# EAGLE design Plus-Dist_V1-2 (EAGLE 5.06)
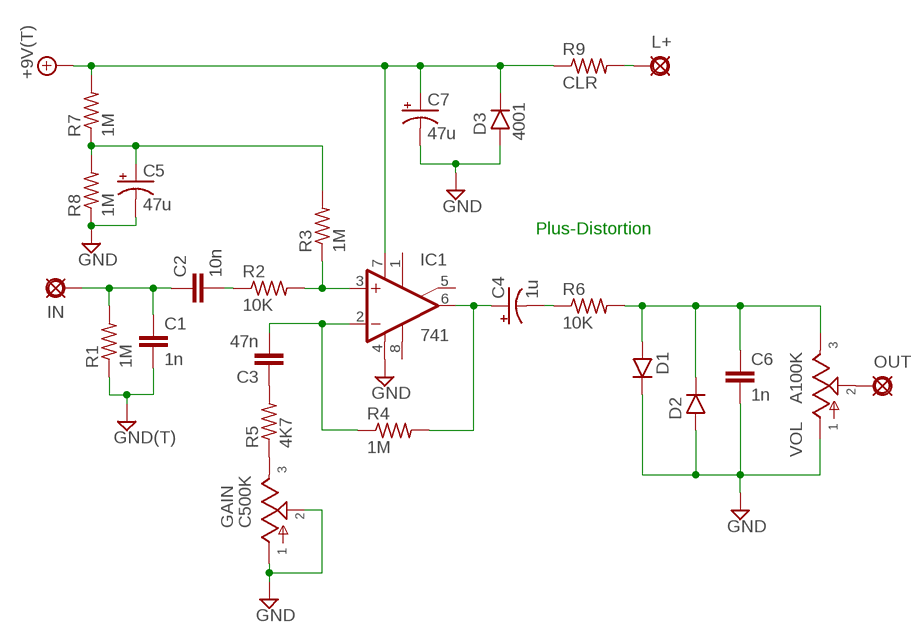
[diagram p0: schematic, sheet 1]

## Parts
+9V  +9V(T)  [SQUARE]
C1  1n  072X0252  [072X025]
C2  10n  072X0252  [072X025]
C3  47n  072X0252  [072X025]
C4  1u  0501  [050_020_1]
C5  47u  0501  [050_020_1]
C6  1n  072X0252  [072X025]
C7  47u  0501  [050_020_1]
D1  1N400X.4  [DO41-4]
D2  1N400X.4  [DO41-4]
D3  4001  1N400X.3  [DO41-3]
GAIN  C500K  POTPCB  [16MM-PCB-MOUNT]
GND  GND(T)  [SQUARE]
IC1  741  uA741P  [DIL08]
IN  PAD8  [OCTOGON]
L+  L+  PAD8  [OCTOGON]
OUT  PAD8  [OCTOGON]
R1  1M  6MM.3  [R0207/3]
R2  10K  6MM.3  [R0207/3]
R3  1M  6MM.3  [R0207/3]
R4  1M  6MM.3  [R0207/3]
R5  4K7  6MM.3  [R0207/3]
R6  10K  6MM.3  [R0207/3]
R7  1M  6MM.3  [R0207/3]
R8  1M  6MM.3  [R0207/3]
R9  CLR  6MM.3  [R0207/3]
VOL  A100K  POTPCB  [16MM-PCB-MOUNT]

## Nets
+9V: +9V.1(+9V) C7.+ D3.C IC1.7(V+) R7.2 R9.1
GND: C1.2 C5.- C6.2 C7.- D1.C D2.A D3.A GAIN.1 GAIN.2 GND.1(GND) IC1.4(V-) R1.1 R8.1 VOL.1
N$1: C1.1 C2.1 IN.1(PAD) R1.2
N$2: C2.2 R2.1
N$3: IC1.3(+IN) R2.2 R3.1
N$4: C3.2 IC1.2(-IN) R4.1
N$5: C4.+ IC1.6(OUT) R4.2
N$6: C3.1 R5.2
N$7: GAIN.3 R5.1
N$8: C4.- R6.1
N$9: C5.+ R3.2 R7.1 R8.2
N$10: OUT.1(PAD) VOL.2
N$11: C6.1 D1.A D2.C R6.2 VOL.3
N$12: L+.1(PAD) R9.2
Unconnected: IC1.1(ON1) IC1.5(ON2) IC1.8(OPT)

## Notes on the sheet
- Plus-Distortion

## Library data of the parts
+9V = gm-supply:+9V(T): +9V Voltage Supply
C1-C3 C6 = gm-caps-film-box:072X025: 1000pF - 0.47uF
C4 C5 C7 = gm-caps-electro-pol:050: 0.22 - 100uF
D1-D3 = gm-diodes:1N400X: Rectifier Diodes
GAIN VOL = gm-pots_pcb_noscreen:POT: Potentiometers the arrow indicates the clockwise motion of th wiper (lug 2) fully counter clockwise there is no resistance between lugs 1 and 2 fully clockwise the resistance between lugs 1 and 2 is the value of the pot
GND = gm-supply:GND(T): Ground
IC1 = gm-ics:*741: OP AMP
IN L+ OUT = gm-supply:PAD: PAD
R1-R9 = gm-resistors:6MM: 6mm Resistors

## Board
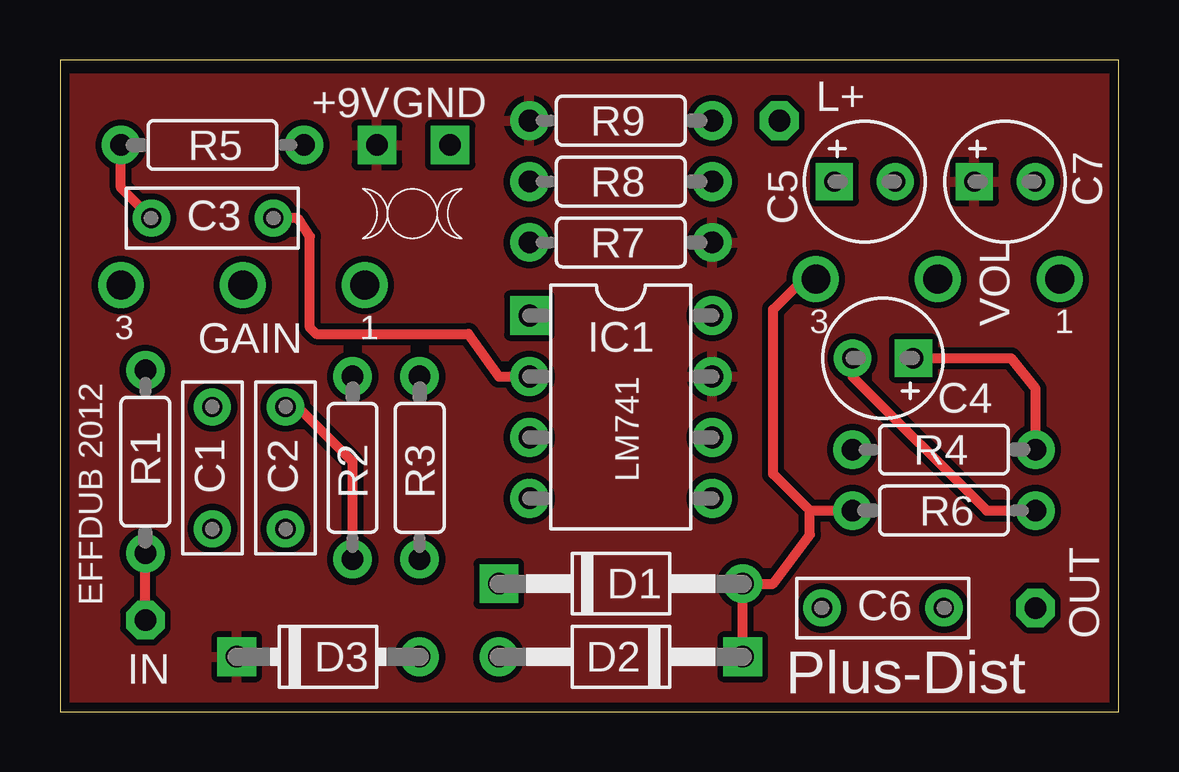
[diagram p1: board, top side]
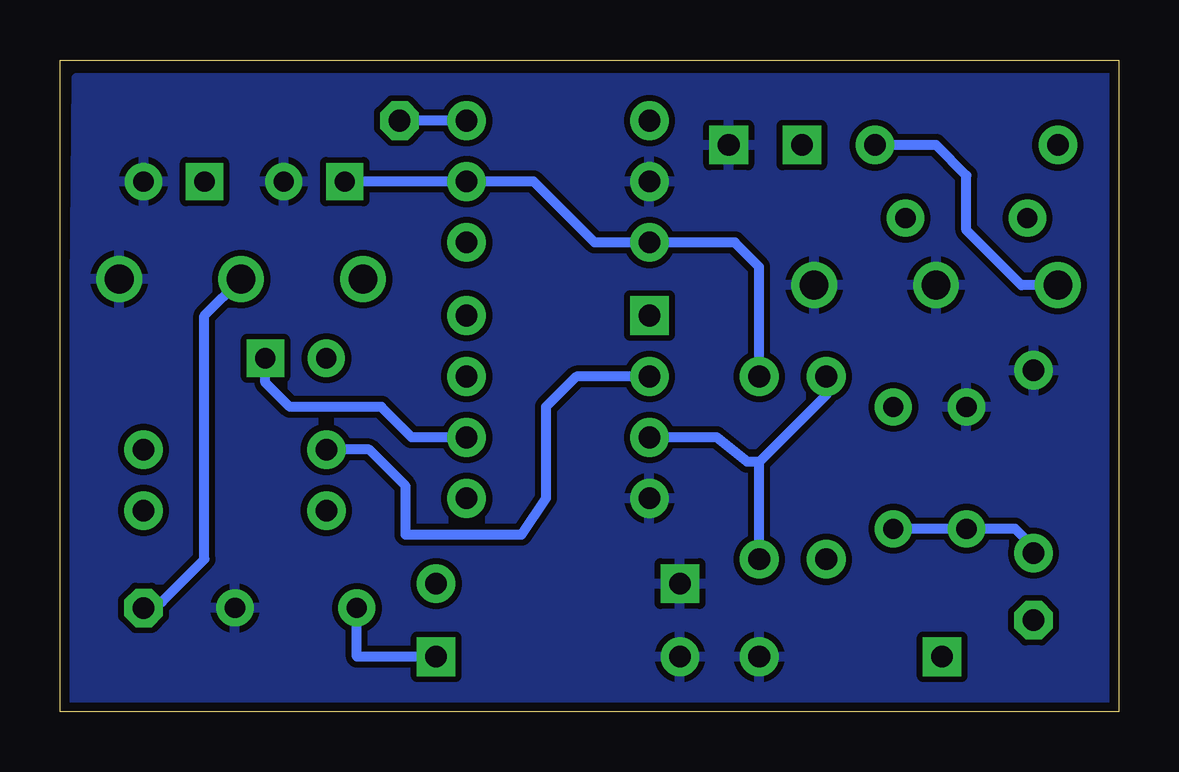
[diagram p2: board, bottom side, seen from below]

Size 44.12 x 27.17 mm. Coordinates in mm from the lower left corner, seen from the top.
Outline: 0,0 44.12,0 44.12,27.17 0,27.17 0,0
Copper layers (1*16): Top 0.035mm / dielectric 1.5mm / Bottom 0.035mm
Design rules "ITEADstudio_DRC *": minimum track width 6mil, minimum drill 12mil, track to track 10mil, track to pad 10mil, pad to pad 10mil, via to via 6mil, smd to smd 0mil, copper to edge 15mil, drill to drill 10mil, minimum pad ring 14mil, minimum via ring 8mil, stop-mask expansion 2mil, vias tented up to drill 100mil, thermal gap 10mil

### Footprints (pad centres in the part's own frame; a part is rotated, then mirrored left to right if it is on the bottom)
SQUARE = drill 0.9 square: 1 0,0
072X025 = drill 0.838 round: 1 -2.54,0; 2 2.54,0
050_020_1 = drill 0.838 square: + -1.27,0 | drill 0.838 round: - 1.27,0
DO41-4 = drill 0.9 round: A 5.08,0 | drill 0.9 square: C -5.08,0
DO41-3 = drill 0.9 round: A 3.81,0 | drill 0.9 square: C -3.81,0
16MM-PCB-MOUNT = drill 1.2 round: 1 5.08,0; 2 0,0; 3 -5.08,0
DIL08 = drill 0.9 square: 1 -3.81,-3.81 | drill 0.9 round: 2 -1.27,-3.81; 3 1.27,-3.81; 4 3.81,-3.81; 5 3.81,3.81; 6 1.27,3.81; 7 -1.27,3.81; 8 -3.81,3.81
OCTOGON = drill 0.9 octagon: 1 0,0
R0207/3 = drill 0.9 round: 1 -3.81,0; 2 3.81,0

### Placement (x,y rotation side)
+9V  13.21,23.62 90 top
C1  6.35,10.16 90 top
C2  9.4,10.16 90 top
C3  6.35,20.57 0 top
C4  34.29,14.73 180 top
C5  33.53,22.1 0 top
C6  34.29,4.32 0 top
C7  39.37,22.1 0 top
D1  23.37,5.33 0 top
D2  23.37,2.29 180 top
D3  11.18,2.29 0 top
GAIN  7.62,17.78 0 top
GND  16.26,23.62 90 top
IC1  23.37,12.7 270 top
IN  3.56,3.81 0 top
L+  29.97,24.64 0 top
OUT  40.64,4.32 0 top
R1  3.56,10.41 270 top
R2  12.19,10.16 90 top
R3  14.99,10.16 90 top
R4  36.83,10.92 0 top
R5  6.35,23.62 180 top
R6  36.83,8.38 180 top
R7  23.37,19.56 0 top
R8  23.37,22.1 0 top
R9  23.37,24.64 0 top
U$1  [LOGO]  16.76,21.84 180 top
VOL  36.58,18.03 0 top

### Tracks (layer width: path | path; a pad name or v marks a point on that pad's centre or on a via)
+9V
  pour Top: 0.51,26.42 43.69,26.42 43.69,0.51 0.51,0.51
GND
  pour Bottom: 0.25,26.42 43.43,26.42 43.69,0.51 0.51,0.51
N$1
  Top 0.406: IN.1 R1.2
  Bottom 0.406: R1.2 3.56,6.86 4.32,7.62 C1.1 C2.1
N$2
  Top 0.406: C2.2 9.91,12.7 12.19,10.41 R2.1
N$3
  Bottom 0.406: R2.2 12.19,13.21 14.99,10.41 | R3.1 14.99,10.41 | IC1.3 16.76,11.43 15.49,10.41 14.99,10.41
N$4
  Top 0.406: C3.2 9.91,20.57 10.41,19.81 10.41,16 10.67,15.75 17.02,15.75 18.29,13.97 IC1.2
  Bottom 0.406: IC1.2 22.61,13.97 23.88,12.7 23.88,8.89 24.89,7.37 29.72,7.37 29.72,9.4 31.24,10.92 R4.1
N$5
  Top 0.406: R4.2 40.64,13.46 39.62,14.73 C4.+
  Bottom 0.406: IC1.6 29.46,11.43 30.73,12.7 34.54,12.7 35.56,13.72 C4.+
N$6
  Top 0.406: C3.1 2.54,21.84 R5.2
N$7
  Bottom 0.406: GAIN.3 4.06,17.78 6.35,20.07 6.35,22.35 7.62,23.62 R5.1
N$8
  Top 0.406: C4.- 33.02,13.97 38.61,8.38 R6.1
N$9
  Bottom 0.406: R3.2 14.99,18.54 16,19.56 R7.1 21.84,19.56 24.38,22.1 R8.2 C5.+
N$10
  Bottom 0.406: VOL.2 38.1,16.51 38.1,6.35 39.88,4.57 OUT.1
N$11
  Top 0.406: D2.C D1.A 29.72,5.33 31.24,7.37 31.24,8.38 | VOL.3 30.99,18.03 29.72,16.76 29.72,9.91 31.24,8.38 | 31.24,8.38 R6.2
  Bottom 0.406: D2.C 31.75,2.29 C6.1
N$12
  Bottom 0.406: R9.2 L+.1

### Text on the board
tNames: EFFDUB 2012 | LM741 | Plus-Dist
